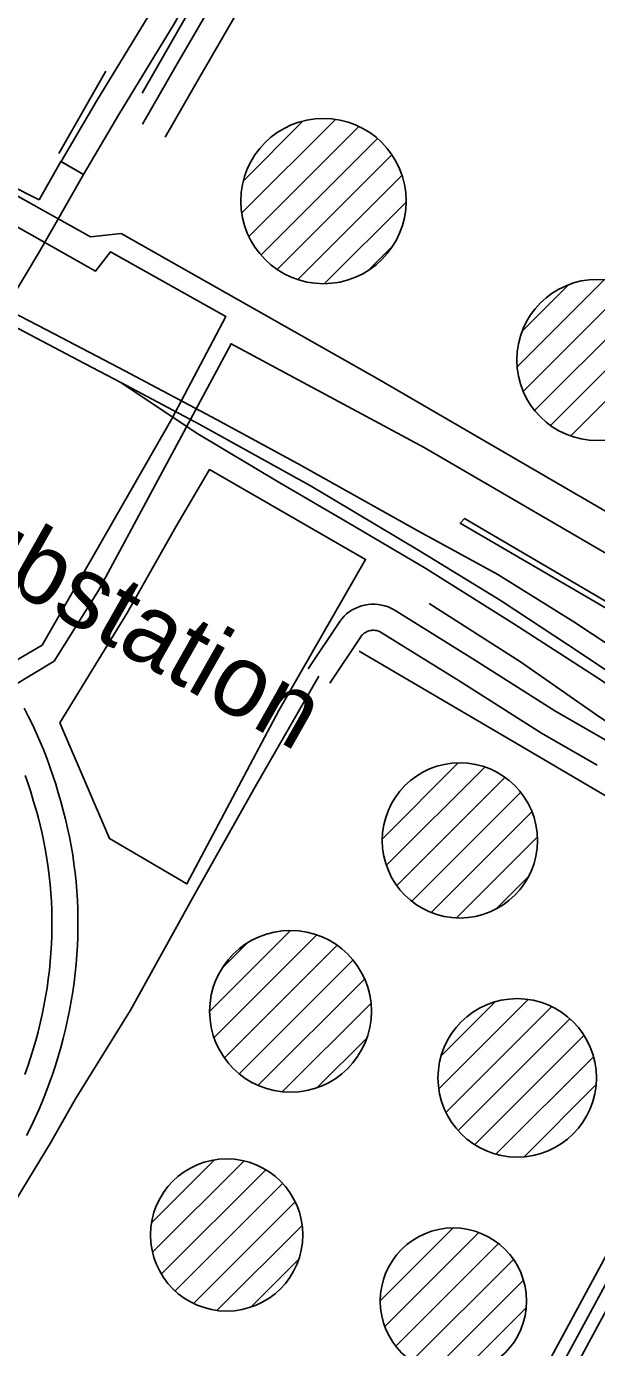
# Model space of a CAD drawing. Extents: x 3568792 to 3606828, y 529143 to 554785.
# Drawn here: x 3576994 to 3577651, y 544184 to 545708 of the extents above; entities that cross this region are included whole.
import ezdxf

# ---------------------------------------------------------------- set-up
doc = ezdxf.new("R2010")
doc.units = 0
for name, color, linetype in [('V-DOMW-TANK', 7, 'Continuous'), ('V-RAIL-TRAK', 7, 'Continuous'), ('V-ROAD-CNTR', 7, 'Continuous'), ('V-SITE-OTLN', 7, 'Continuous'), ('V-SITE-OTLN-IDEN', 7, 'Continuous'), ('V-TOPO-SHOR', 7, 'Continuous'), ('V-UTIL-LINE', 7, 'Continuous')]:
    doc.layers.add(name, color=color, linetype=linetype)

msp = doc.modelspace()

# ---------------------------------------------------------------- linework, layer by layer
at = {"layer": 'V-DOMW-TANK'}
for p, q in [((3577242.1, 545492.5), (3577350, 545600.4)), ((3577243.9, 545529.7), (3577312.5, 545598.2)), ((3577250.3, 545465.4), (3577377.1, 545592.1)), ((3577264.3, 545444), (3577398.6, 545578.3)), ((3577283.1, 545427.4), (3577415.1, 545559.4)), ((3577306.9, 545415.8), (3577426.7, 545535.6)), ((3577337.5, 545411.1), (3577431.5, 545505.1)), ((3577388.7, 545426.9), (3577415.5, 545453.8)), ((3577559.6, 545315), (3577660.1, 545415.5)), ((3577565.5, 545356.2), (3577618.8, 545409.6)), ((3577566.7, 545286.7), (3577688.5, 545408.5)), ((3577579.8, 545264.5), (3577710.6, 545395.3)), ((3577598.1, 545247.4), (3577727.6, 545377)), ((3577621.4, 545235.4), (3577739.7, 545353.7)), ((3577404.2, 544770.7), (3577491.7, 544858.2)), ((3577409, 544740.2), (3577522.2, 544853.3)), ((3577421, 544716.8), (3577545.5, 544841.3)), ((3577438.2, 544698.7), (3577563.7, 544824.1)), ((3577460.6, 544685.7), (3577576.6, 544801.7)), ((3577489.8, 544679.5), (3577582.8, 544772.5)), ((3577535, 544689.4), (3577572.8, 544727.2)), ((3577205.2, 544571.7), (3577298.3, 544664.8)), ((3577210.3, 544541.4), (3577328.6, 544659.7)), ((3577219.8, 544621.6), (3577248.3, 544650.1)), ((3577222.2, 544518), (3577352, 544647.8)), ((3577239.2, 544499.6), (3577370.3, 544630.7)), ((3577261.1, 544486.2), (3577383.7, 544608.8)), ((3577289.2, 544479), (3577391, 544580.7)), ((3577469.4, 544482.3), (3577572.2, 544585.2)), ((3577472.1, 544520.4), (3577534.3, 544582.6)), ((3577477.6, 544455.2), (3577599.3, 544576.9)), ((3577491.8, 544434), (3577620.5, 544562.8)), ((3577329.5, 544483.9), (3577386, 544540.4)), ((3577510.9, 544417.8), (3577636.7, 544543.6)), ((3577535.4, 544407), (3577647.6, 544519.1)), ((3577567.8, 544403.9), (3577650.5, 544486.7)), ((3577138.3, 544328.1), (3577210.3, 544400)), ((3577139.3, 544293.7), (3577244.6, 544398.9)), ((3577149.5, 544268.6), (3577269.8, 544388.8)), ((3577165.4, 544249), (3577289.2, 544372.9)), ((3577186.4, 544234.7), (3577303.5, 544351.8)), ((3577213.7, 544226.7), (3577311.6, 544324.6)), ((3577401.9, 544238), (3577485.4, 544321.6)), ((3577407.1, 544207.9), (3577515.5, 544316.3)), ((3577419.8, 544185.3), (3577538.1, 544303.6)), ((3577253.1, 544230.7), (3577307.6, 544285.2)), ((3577438, 544168.1), (3577555.3, 544285.4)), ((3577461.9, 544156.6), (3577566.8, 544261.5)), ((3577494.1, 544153.5), (3577569.8, 544229.2))]:
    msp.add_line(p, q, dxfattribs=at)
for centre, radius in [((3577336.3, 545506.2), 95.3), ((3577652.2, 545322.9), 93), ((3577493.6, 544768.7), 89.5), ((3577298.3, 544571.6), 93.3), ((3577559.7, 544494.8), 91.4), ((3577224.7, 544313.6), 87.8), ((3577486.1, 544237.3), 84.4)]:
    msp.add_circle(centre, radius, dxfattribs=at)
at = {"layer": 'V-RAIL-TRAK'}
for points in [[(3576442.5, 545653.1), (3576566.5, 545591.5), (3576666.9, 545539.9), (3576763.3, 545491), (3576857.8, 545440.8), (3576956.5, 545388.7), (3577025.7, 545352.9), (3577107.2, 545310.4), (3577213, 545254.2), (3577307.1, 545203.1), (3577446, 545125.3), (3577537.4, 545075.5), (3577625.1, 545020.7), (3577733.7, 544948.8), (3577824.2, 544887.2), (3577944.1, 544799), (3578049.9, 544715.7)], [(3576949.8, 545377.1), (3577053.4, 545322.8), (3577102.6, 545296.8), (3577193.7, 545248.6), (3577322.1, 545177.5), (3577447, 545102.9), (3577541.1, 545044.9), (3577633.4, 544984.3), (3577743.3, 544910.5), (3577862.7, 544824.6), (3577962.7, 544749.4), (3578074, 544660.7), (3578165.3, 544586.5), (3578271.2, 544494.2), (3578367.5, 544407.8), (3578466.6, 544312.8), (3578565.7, 544214.1), (3578656.6, 544118.2)], [(3577102.6, 545296.8), (3577189.6, 545239), (3577285.8, 545181.3), (3577366.5, 545134.1), (3577454.4, 545082.3), (3577555.7, 545018.6), (3577655.5, 544954.4), (3577808.5, 544846.7), (3577910.2, 544773), (3578008.7, 544697.3), (3578071.9, 544645.1), (3578159.9, 544572.2), (3578242.4, 544503.5), (3578329.8, 544424.7), (3578451.2, 544308.8), (3578536.4, 544224.4), (3578627.1, 544129.6)]]:
    msp.add_lwpolyline(points, dxfattribs=at)
at = {"layer": 'V-ROAD-CNTR'}
for points in [[(3577400, 546125.2), (3577373.3, 546077.9), (3577303.5, 545952.5), (3577238.3, 545840.8), (3577164.3, 545710.8), (3577100.4, 545605.9), (3577059.5, 545536.7), (3577033.7, 545552), (3577074.7, 545621.4), (3577138.5, 545726), (3577212.3, 545855.8), (3577277.4, 545967.4), (3577302.8, 546013)], [(3577430.4, 546109.8), (3577403.9, 546064.7), (3577353.2, 545979.2), (3577304.4, 545897.5), (3577258.6, 545823.1), (3577216.4, 545748.8), (3577167.6, 545664.6), (3577127.7, 545594.9)], [(3577457.3, 546096.3), (3577429.7, 546049.4), (3577379, 545963.9), (3577330.1, 545881.9), (3577284.4, 545807.8), (3577242.5, 545733.8), (3577193.6, 545649.7), (3577153.8, 545580)], [(3576524.6, 545745.9), (3576655.5, 545690.4), (3576680.3, 545673.5), (3577008.4, 545507.6)], [(3577008.4, 545507.7), (3577033.5, 545551.8), (3577059.6, 545536.9), (3577024.9, 545476), (3577008.9, 545447.9), (3576975.7, 545392.5), (3576969.6, 545381.3), (3576962.8, 545369.7), (3576961.6, 545367.5), (3576927.8, 545306.7), (3576898.2, 545258.5), (3576879.1, 545227.5), (3576845.4, 545163.8), (3576820.7, 545122.2)], [(3577318.6, 544966.6), (3577355, 545021.3), (3577357.4, 545024.4), (3577360, 545027.3), (3577362.9, 545029.9), (3577366.1, 545032.3), (3577369.3, 545034.5), (3577372.8, 545036.3), (3577376.4, 545037.9), (3577380.1, 545039.2), (3577383.9, 545040.2), (3577387.8, 545040.8), (3577391.7, 545041.1), (3577395.6, 545041.1), (3577399.5, 545040.8), (3577403.4, 545040.2), (3577407.2, 545039.3), (3577410.9, 545038), (3577414.6, 545036.4), (3577417.9, 545034.7), (3577508.6, 544978.3), (3577603.2, 544918.2), (3577666.6, 544881.5)], [(3577343.6, 544950), (3577379.3, 545003.7), (3577380.2, 545004.9), (3577381.2, 545006), (3577382.3, 545007), (3577383.4, 545007.9), (3577384.7, 545008.7), (3577386, 545009.4), (3577387.3, 545009.9), (3577388.7, 545010.4), (3577390.1, 545010.8), (3577391.5, 545011), (3577393, 545011.1), (3577394.5, 545011.1), (3577395.9, 545011), (3577397.4, 545010.8), (3577398.8, 545010.4), (3577400.2, 545010), (3577401.5, 545009.4), (3577402.9, 545008.6), (3577492.7, 544952.9), (3577587.6, 544892.6), (3577651.8, 544855.5)], [(3577331.1, 544958.3), (3577257.7, 544830.7), (3577185.2, 544702.2), (3577113.7, 544572.8), (3577050.3, 544470.7), (3577021.1, 544419.2), (3576970.1, 544334.9)], [(3576993.9, 544428.3), (3576998.7, 544438), (3577003.4, 544447.9), (3577007.9, 544457.8), (3577012.2, 544467.9), (3577016.2, 544478), (3577020.1, 544488.2), (3577023.7, 544498.5), (3577027.2, 544508.9), (3577030.4, 544519.3), (3577033.5, 544529.8), (3577036.3, 544540.4), (3577038.9, 544551), (3577041.3, 544561.7), (3577043.5, 544572.4), (3577045.4, 544583.1), (3577047.2, 544593.9), (3577048.7, 544604.7), (3577050, 544615.6), (3577051.1, 544626.4), (3577051.9, 544636.9), (3577052.6, 544647.4), (3577053, 544657.9), (3577053.2, 544668.4), (3577053.2, 544678.9), (3577053, 544689.4), (3577052.5, 544699.9), (3577051.9, 544710.3), (3577051, 544720.8), (3577049.9, 544731.3), (3577048.6, 544741.7), (3577047.1, 544752.1), (3577045.3, 544762.4), (3577043.4, 544772.8), (3577041.2, 544783), (3577038.8, 544793.3), (3577036.2, 544803.4), (3577033.4, 544813.6), (3577030.5, 544823.5), (3577027.5, 544833.5), (3577024.3, 544843.6), (3577020.8, 544853.6), (3577017.2, 544863.5), (3577013.3, 544873.4), (3577009.3, 544883.1), (3577005, 544892.8), (3577000.6, 544902.4), (3576995.9, 544911.9), (3576991.1, 544921.3)], [(3576991.9, 544498.6), (3576995.4, 544508.3), (3576998.6, 544518.1), (3577001.7, 544527.9), (3577004.6, 544537.9), (3577007.2, 544547.8), (3577009.7, 544557.9), (3577011.9, 544567.9), (3577014, 544578), (3577015.8, 544588.2), (3577017.5, 544598.4), (3577018.9, 544608.6), (3577020.2, 544618.9), (3577021.2, 544629.1), (3577022, 544639), (3577022.6, 544648.9), (3577023, 544658.8), (3577023.2, 544668.6), (3577023.2, 544678.5), (3577023, 544688.4), (3577022.6, 544698.3), (3577022, 544708.1), (3577021.1, 544718), (3577020.1, 544727.8), (3577018.9, 544737.6), (3577017.4, 544747.4), (3577015.8, 544757.2), (3577014, 544766.9), (3577011.9, 544776.5), (3577009.7, 544786.2), (3577007.2, 544795.8), (3577004.6, 544805.3), (3577001.7, 544814.9), (3576998.8, 544824.6), (3576995.8, 544834.1), (3576992.5, 544843.5)], [(3576880.6, 542873.3), (3576897.4, 542894), (3576916.9, 542921.6), (3577159.8, 543354.8), (3577380.1, 543731.5), (3577386.9, 543744.7), (3577391.9, 543755), (3577399.8, 543775.1), (3577466.1, 543997.9), (3577473.5, 544013.4), (3577487, 544044.8), (3577508.6, 544072), (3577524.9, 544083.5), (3577542.7, 544093.1), (3577556, 544101.8), (3577569, 544117.2), (3577747.7, 544447.5)], [(3576792.6, 542747.3), (3576849.8, 542817.2), (3576876.2, 542843.7), (3576886.7, 542857.1), (3576909.3, 542884.9), (3576929.6, 542913.6), (3577172.8, 543347.3), (3577393.2, 543724.2), (3577400.3, 543738), (3577405.7, 543748.9), (3577414, 543770.3), (3577480.1, 543992.4), (3577487.2, 544007.2), (3577500, 544037), (3577519, 544061), (3577532.8, 544070.8), (3577550.4, 544080.1), (3577566, 544090.4), (3577581.5, 544108.7), (3577760.9, 544440.3)], [(3577575, 544078.4), (3577576.1, 544079.1), (3577593.9, 544100.1), (3577774.1, 544433.2)]]:
    msp.add_lwpolyline(points, dxfattribs=at)
at = {"layer": 'V-SITE-OTLN'}
msp.add_lwpolyline([(3577032.2, 544904.4), (3577109.6, 545030.6), (3577166.1, 545130.3), (3577204.9, 545196.4), (3577384.8, 545092.9), (3577285, 544918.5), (3577178.8, 544718.5), (3577089.6, 544770.9)], close=True, dxfattribs=at)
at = {"layer": 'V-TOPO-SHOR'}
msp.add_line((3577031, 545561.1), (3577085.5, 545655.9), dxfattribs=at)
for points in [[(3577127.2, 545630.8), (3577340.9, 546004.1), (3577403.5, 546111.1)], [(3577458, 545041.9), (3577563.7, 544974.8), (3577650.1, 544914.5), (3577765.5, 544836.8), (3577812.9, 544809.2), (3577840, 544788), (3577848.3, 544773.8), (3577849.9, 544751.2)], [(3577377.3, 544986.9), (3577553.2, 544883.8), (3577706.2, 544794), (3577745.1, 544779.8), (3577812, 544759.2)]]:
    msp.add_lwpolyline(points, dxfattribs=at)
at = {"layer": 'V-UTIL-LINE'}
for points in [[(3576463, 545507.9), (3576471.7, 545523.6), (3576592.1, 545455.1), (3576685.9, 545624.6), (3576953.8, 545493.3), (3576972.9, 545517.9), (3577067.7, 545465.1), (3577103.2, 545468.7), (3577401.1, 545300.1), (3577684.4, 545135.2), (3577935, 545565.2), (3578062.6, 545793.8), (3578248.5, 545683.5), (3578288.6, 545763.7)], [(3576456.1, 544013.4), (3576639.2, 544329.9), (3576823.8, 544648.3), (3576944.1, 544849.2), (3576879, 544886.1), (3576891.7, 544918.9), (3576828.9, 544952.2), (3576837.5, 544963.1), (3576898.1, 544927.6), (3577012, 544994.1), (3577161.5, 545255.1), (3577223.9, 545373), (3577090.9, 545447.8), (3577073.6, 545425.5), (3576965.6, 545486.5), (3576954.2, 545468.8), (3576687.7, 545601.8), (3576602.1, 545436), (3576589.4, 545442.4)], [(3577707.2, 545073.7), (3577452.5, 545221.8), (3577229.8, 545341.6), (3577076.7, 545056.9), (3577025.7, 544975.4), (3576906.3, 544903.4)], [(3577842.8, 544485.7), (3578153, 544483.9), (3578270.1, 544682.5), (3577742.7, 544989.6), (3577494, 545134.5), (3577499, 545140), (3577974.5, 544861.1), (3578280.2, 544685.2), (3578158.5, 544475.7), (3577841.4, 544479.4), (3577828.2, 544457.5), (3577765.8, 544493.1), (3577760.3, 544487.1), (3577729.4, 544505.4), (3577743.5, 544527.2)]]:
    msp.add_lwpolyline(points, dxfattribs=at)

# ---------------------------------------------------------------- texts
at = {"layer": 'V-SITE-OTLN-IDEN'}
msp.add_text('Substation', height=83, rotation=330.509, dxfattribs=at).set_placement((3576848.5, 545129.1))

doc.saveas('drawing.dxf')
